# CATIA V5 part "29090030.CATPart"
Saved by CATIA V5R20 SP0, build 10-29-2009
Part number: 29090030
Definition: NONE
Nomenclature: 29090030
Source: Unknown
Description: 29090030
Bounding box of the stored display mesh (mm): x -15 to 44.548, y -59 to 93.548, z -49 to 49
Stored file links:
  C:\Users\Utente\Desktop\IO LAVORO\3D X SITO CF\X SITO\PLASTICA\RF1\29090030.CATPart
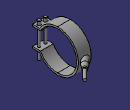
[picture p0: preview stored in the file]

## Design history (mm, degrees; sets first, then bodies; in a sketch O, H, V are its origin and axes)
Body1 "29090030" (main body)
  Solid1: solid without history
